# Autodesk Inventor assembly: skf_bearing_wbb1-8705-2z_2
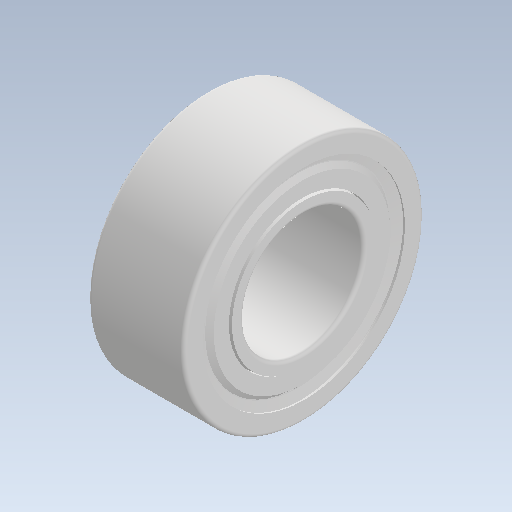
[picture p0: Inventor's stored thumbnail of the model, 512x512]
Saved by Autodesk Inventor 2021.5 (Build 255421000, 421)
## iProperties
Company: TraceParts S.A.
Created: 2023-11
Part Number: skf_bearing_wbb1-8705-2z_2
Checked By: TraceParts S.A.
Catalog Web Link: www.traceparts.com
Document SubType Name: Assembly
Designer: TraceParts
Author: TraceParts
Sending System: TraceParts v2
Major Version: 6.0
Minor Version: 0.0
Format Version: 0.0
Product Id: TraceParts v2
REFERENCE: WBB1-8705-2Z
SUPPLIER: SKF
DESIGN: Stainless steel single row deep groove ball bearing, shields, Bore Ø 5 mm, Outside Ø 10 mm
MASS: 0.00122
TraceParts.PartNumber: 10-28092016-118829
TraceParts.PartVersion: 1.3.2
TraceParts.InstanceId: 10-28092016-118829DU1G261IQ8J2U3VLH6ZEA37AO
TraceParts.PartTitle: Deep groove ball bearings, single row, stainless steel, shields
TRACEPARTS: TRACEPARTS
TraceParts.PartLanguage: en
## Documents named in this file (6)
- C:\TPO v2\SharedFS\Outgoing\skf_bearing_wbb1-8705-2z_2.iam
- C:\TPO v2\SharedFS\Outgoing\skf_bearing_wbb1-8705-2z_2_01.ipt
- C:\TPO v2\SharedFS\Outgoing\skf_bearing_wbb1-8705-2z_2_02.ipt
- C:\TPO v2\SharedFS\Outgoing\skf_bearing_wbb1-8705-2z_2_03.ipt
- C:\TPO v2\SharedFS\Outgoing\skf_bearing_wbb1-8705-2z_2_04.ipt
- C:\TPO v2\SharedFS\Outgoing\skf_bearing_wbb1-8705-2z_2_05.ipt
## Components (5 placed, 5 different names)
1. skf_bearing_wbb1-8705-2z_2_Temp_1:1
2. skf_bearing_wbb1-8705-2z_2_Temp_2:1
3. skf_bearing_wbb1-8705-2z_2_Temp_3:1
4. skf_bearing_wbb1-8705-2z_2_Temp_4:1
5. skf_bearing_wbb1-8705-2z_2_Temp_5:1
